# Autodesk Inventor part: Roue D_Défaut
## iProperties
Shininess: 64.0
Length Units: 11269
Angle Units: 11279
Time Units: 11290
Mass Units: 11283
Length Display Precision: 3
Angle Display Precision: 2
Compacted: True
Part Number: Roue D_Défaut
Document SubType Name: Modeling
Created: 2006-01
Material: Par défaut
Designer: Fricot
Density: 0.0
Volumn: 0.0
Area: 0.0
PropertySet Name: Model Information
Control State: 0
Master: False
Checked Out: False
Author: Fricot
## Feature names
1. Base1
